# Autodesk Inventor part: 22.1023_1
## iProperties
Created: 2007-11
Part Number: 22.1023_1
Material: ABS Plastic
Document SubType Name: Modeling
Designer: Andy Moles
Mass: 2.08108 g
Surface Area: 22.4529 cm^2
Volume: 1.96328 cm^3
Density: 1.06 g/cm^3
Description: End Cap For Handle Profile 32
Vendor: S
Author: Andy Moles
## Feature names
1. Base1
